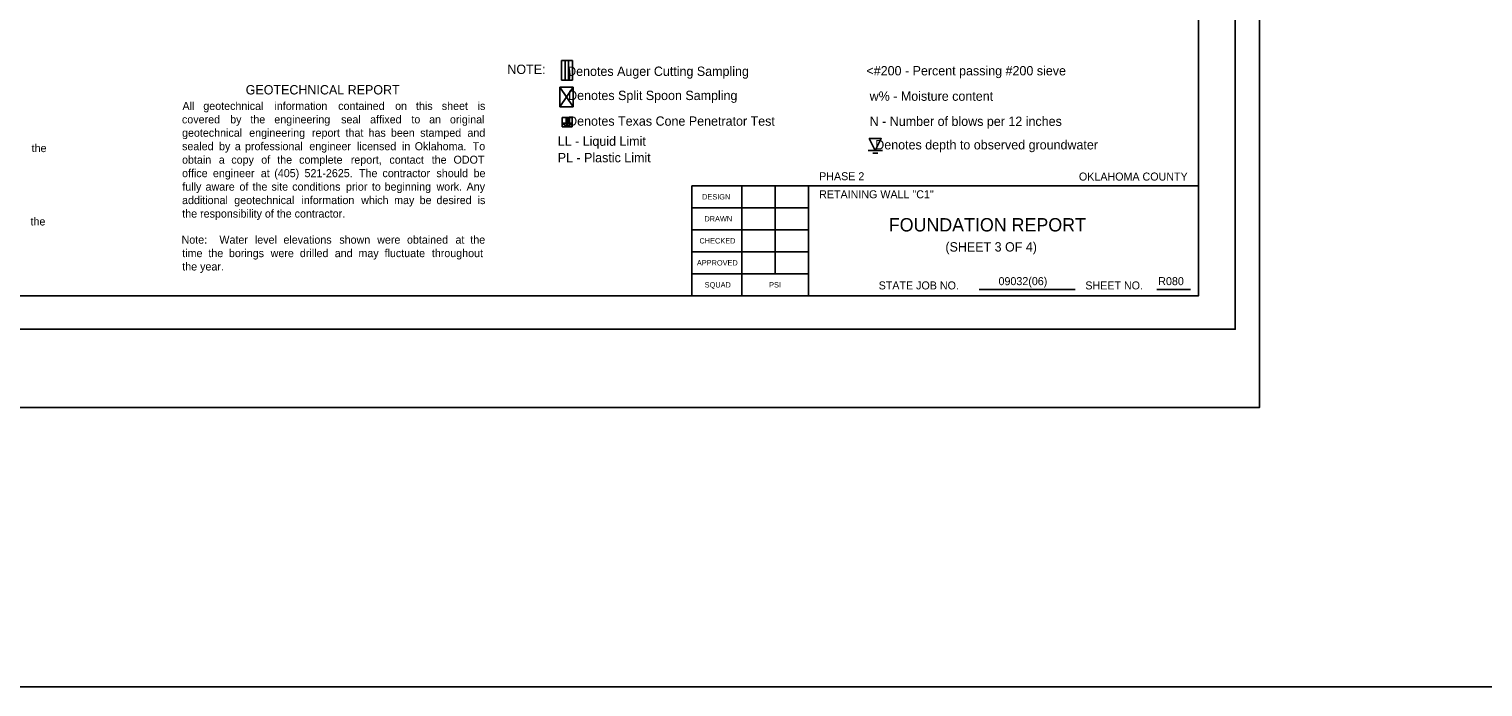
# Model space of a CAD drawing. Extents: x -6 to 173, y 24 to 64.
# Drawn here: x 107.52 to 129.33, y 25.78 to 35.65 of the extents above; entities that cross this region are included whole.
import ezdxf

# ---------------------------------------------------------------- set-up
doc = ezdxf.new("R2010")
doc.units = 0
for name, color, linetype in [('4', 7, 'Continuous'), ('S', 7, 'Continuous'), ('SHT_Plot_Shape_Full', 7, 'Continuous'), ('SHT_Plot_Shape_Half', 7, 'Continuous'), ('SHT_Sheet_Border', 7, 'Continuous'), ('SHT_Standard_Sheet_Lines', 7, 'Continuous'), ('SHT_Standard_Sheet_Txt', 7, 'Continuous'), ('T', 7, 'Continuous'), ('T-5', 7, 'Continuous'), ('Text', 7, 'Continuous')]:
    doc.layers.add(name, color=color, linetype=linetype)

# ---------------------------------------------------------------- blocks, each defined once
blk = doc.blocks.new('DGRFC_WTLEV1_1')
for points in [[(-0.005, 0), (0.005, 0)], [(0, 0), (0.0042, 0.0083), (-0.0042, 0.0083), (0, 0)], [(-0.0017, -0.0017), (0.0017, -0.0017)]]:
    blk.add_lwpolyline(points)

msp = doc.modelspace()

# ---------------------------------------------------------------- linework, layer by layer
msp.add_line((115.51, 35.172), (115.51, 34.881))
for points in [[(115.51, 35.172), (115.676, 35.172)], [(115.676, 34.881), (115.676, 35.172)], [(115.51, 34.881), (115.676, 34.881)], [(115.51, 34.881), (115.676, 34.881)]]:
    msp.add_lwpolyline(points)
for points in [[(115.568, 35.172), (115.568, 34.881), (115.618, 34.881), (115.618, 35.172)], [(115.633, 35.005), (115.627, 35.047), (115.618, 35.087), (115.633, 35.005)], [(115.618, 35.087), (115.618, 34.881), (115.633, 35.005), (115.618, 35.087)], [(115.618, 34.881), (115.633, 34.922), (115.633, 35.005), (115.618, 34.881)], [(115.618, 34.881), (115.627, 34.881), (115.633, 34.922), (115.618, 34.881)], [(115.633, 34.922), (115.635, 34.963), (115.633, 35.005), (115.633, 34.922)]]:
    msp.add_lwpolyline(points, close=True)
at = {"layer": 'S'}
msp.add_lwpolyline([(-6.024, 64.421), (172.576, 64.421), (172.576, 25.783), (-6.024, 25.783)], close=True, dxfattribs=at)
at = {"layer": 'SHT_Plot_Shape_Full'}
msp.add_lwpolyline([(89.979, 53.971), (125.979, 53.971), (125.979, 29.971), (89.979, 29.971)], close=True, dxfattribs=at)
at = {"layer": 'SHT_Plot_Shape_Half'}
msp.add_lwpolyline([(91.616, 53.146), (125.616, 53.146), (125.616, 31.146), (91.616, 31.146)], close=True, dxfattribs=at)
at = {"layer": 'SHT_Sheet_Border'}
for p, q in [((117.466, 31.646), (117.466, 33.296)), ((117.466, 33.296), (125.066, 33.296)), ((119.216, 31.646), (119.216, 33.297))]:
    msp.add_line(p, q, dxfattribs=at)
msp.add_lwpolyline([(93.566, 52.646), (125.066, 52.646), (125.066, 31.646), (93.566, 31.646)], close=True, dxfattribs=at)
at = {"layer": 'SHT_Standard_Sheet_Lines'}
for p, q in [((118.216, 31.646), (118.216, 33.297)), ((118.716, 31.976), (118.716, 33.297)), ((121.777, 31.742), (123.217, 31.742)), ((124.442, 31.742), (124.944, 31.742))]:
    msp.add_line(p, q, dxfattribs=at)
for points in [[(119.216, 32.966), (117.466, 32.966)], [(119.216, 32.636), (117.466, 32.636)], [(119.216, 32.306), (117.466, 32.306)], [(119.216, 31.976), (117.466, 31.976)]]:
    msp.add_lwpolyline(points, dxfattribs=at)
at = {"layer": 'Text'}
for p, q in [((115.486, 34.481), (115.486, 34.773)), ((115.522, 34.181), (115.522, 34.322))]:
    msp.add_line(p, q, dxfattribs=at)
for points in [[(115.486, 34.481), (115.686, 34.773)], [(115.486, 34.773), (115.686, 34.481)], [(115.486, 34.773), (115.686, 34.773)], [(115.686, 34.481), (115.686, 34.773)], [(115.486, 34.481), (115.686, 34.481)], [(115.522, 34.322), (115.672, 34.322)], [(115.672, 34.181), (115.672, 34.322)], [(115.522, 34.181), (115.672, 34.181)]]:
    msp.add_lwpolyline(points, dxfattribs=at)
for points in [[(115.582, 34.237), (115.612, 34.322), (115.582, 34.322), (115.582, 34.237)], [(115.582, 34.237), (115.612, 34.237), (115.612, 34.322), (115.582, 34.237)], [(115.582, 34.237), (115.522, 34.237), (115.597, 34.181), (115.582, 34.237)], [(115.582, 34.237), (115.597, 34.181), (115.612, 34.237), (115.582, 34.237)], [(115.597, 34.181), (115.672, 34.237), (115.612, 34.237), (115.597, 34.181)]]:
    msp.add_lwpolyline(points, close=True, dxfattribs=at)

# ---------------------------------------------------------------- block references
at = {"layer": 'Text', "xscale": 21.6, "yscale": 21.6}
msp.add_blockref('DGRFC_WTLEV1_1', (120.217, 33.823), dxfattribs=at)

# ---------------------------------------------------------------- texts
at = {"layer": '4'}
msp.add_text('FOUNDATION REPORT', height=0.2, dxfattribs=at).set_placement((120.42, 32.611))
at = {"layer": 'SHT_Standard_Sheet_Txt'}
for s, height, p in [('DESIGN', 0.08, (117.619, 33.091)), ('DRAWN', 0.08, (117.654, 32.761)), ('CHECKED', 0.08, (117.58, 32.431)), ('APPROVED', 0.08, (117.541, 32.101)), ('SQUAD', 0.08, (117.658, 31.771)), ('PSI', 0.08, (118.625, 31.771)), ('STATE JOB NO.', 0.12, (120.268, 31.742)), ('SHEET NO. ', 0.12, (123.368, 31.742))]:
    msp.add_text(s, height=height, dxfattribs=at).set_placement(p)
at = {"layer": 'T'}
for s, p in [('PHASE 2', (119.375, 33.379)), ('OKLAHOMA COUNTY', (123.272, 33.374)), ('RETAINING WALL "C1" ', (119.375, 33.108)), ('09032(06)', (122.066, 31.806)), ('R080', (124.462, 31.806))]:
    msp.add_text(s, height=0.12, dxfattribs=at).set_placement(p)
at = {"layer": 'T-5'}
msp.add_text('(SHEET 3 OF 4)', height=0.14, dxfattribs=at).set_placement((121.269, 32.31))
at = {"layer": 'Text'}
for s, height, p in [('NOTE:', 0.14, (114.699, 34.972)), ('    Denotes Auger Cutting Sampling', 0.14, (115.387, 34.943)), (' <#200 - Percent passing #200 sieve', 0.14, (120.033, 34.951)), ('GEOTECHNICAL REPORT', 0.14, (110.774, 34.665)), ('    Denotes Split Spoon Sampling', 0.14, (115.402, 34.581)), ('w% - Moisture content', 0.14, (120.133, 34.57)), ('All', 0.12, (109.825, 34.433)), ('geotechnical', 0.12, (110.138, 34.433)), ('information', 0.12, (111.205, 34.433)), ('contained', 0.12, (112.161, 34.433)), ('on', 0.12, (113.015, 34.433)), ('this', 0.12, (113.328, 34.433)), ('sheet', 0.12, (113.715, 34.433)), ('is ', 0.12, (114.252, 34.433)), ('covered', 0.12, (109.818, 34.231)), ('by', 0.12, (110.541, 34.231)), ('the', 0.12, (110.844, 34.231)), ('engineering', 0.12, (111.203, 34.231)), ('seal', 0.12, (112.205, 34.231)), ('affixed', 0.12, (112.639, 34.231)), ('to', 0.12, (113.259, 34.231)), ('an', 0.12, (113.525, 34.231)), ('original ', 0.12, (113.838, 34.231)), ('    Denotes Texas Cone Penetrator Test', 0.14, (115.402, 34.196)), ('N - Number of blows per 12 inches', 0.14, (120.133, 34.193)), ('geotechnical', 0.12, (109.819, 34.031)), ('engineering', 0.12, (110.826, 34.031)), ('report', 0.12, (111.768, 34.031)), ('that', 0.12, (112.271, 34.031)), ('has', 0.12, (112.616, 34.031)), ('been', 0.12, (112.952, 34.031)), ('stamped', 0.12, (113.391, 34.031)), ('and ', 0.12, (114.099, 34.031)), (' LL - Liquid Limit', 0.14, (115.402, 33.895)), ('the ', 0.12, (107.563, 33.801)), ('sealed', 0.12, (109.819, 33.829)), ('by', 0.12, (110.374, 33.829)), ('a', 0.12, (110.611, 33.829)), ('professional', 0.12, (110.764, 33.829)), ('engineer', 0.12, (111.728, 33.829)), ('licensed', 0.12, (112.443, 33.829)), ('in', 0.12, (113.118, 33.829)), ('Oklahoma.', 0.12, (113.309, 33.829)), ('To ', 0.12, (114.179, 33.829)), ('    Denotes depth to observed groundwater', 0.14, (120.009, 33.841)), ('obtain', 0.12, (109.819, 33.627)), ('a', 0.12, (110.37, 33.627)), ('copy', 0.12, (110.558, 33.627)), ('of', 0.12, (111.007, 33.627)), ('the', 0.12, (111.247, 33.627)), ('complete', 0.12, (111.575, 33.627)), ('report,', 0.12, (112.35, 33.627)), ('contact', 0.12, (112.929, 33.627)), ('the', 0.12, (113.564, 33.627)), ('ODOT ', 0.12, (113.891, 33.627)), (' PL - Plastic Limit', 0.14, (115.402, 33.648)), ('office', 0.12, (109.819, 33.425)), ('engineer', 0.12, (110.282, 33.425)), ('at', 0.12, (111, 33.425)), ('(405)', 0.12, (111.202, 33.425)), ('521-2625.', 0.12, (111.656, 33.425)), ('The', 0.12, (112.473, 33.425)), ('contractor', 0.12, (112.825, 33.425)), ('should', 0.12, (113.635, 33.425)), ('be ', 0.12, (114.192, 33.425)), ('fully', 0.12, (109.823, 33.223)), ('aware', 0.12, (110.172, 33.223)), ('of', 0.12, (110.68, 33.223)), ('the', 0.12, (110.876, 33.223)), ('site', 0.12, (111.16, 33.223)), ('conditions', 0.12, (111.472, 33.223)), ('prior', 0.12, (112.278, 33.223)), ('to', 0.12, (112.667, 33.223)), ('beginning', 0.12, (112.858, 33.223)), ('work.', 0.12, (113.636, 33.223)), ('Any ', 0.12, (114.087, 33.223)), ('the responsibility of the contractor.', 0.12, (109.822, 32.819)), ('additional', 0.12, (109.819, 33.021)), ('geotechnical', 0.12, (110.602, 33.021)), ('information', 0.12, (111.61, 33.021)), ('which', 0.12, (112.506, 33.021)), ('may', 0.12, (113, 33.021)), ('be', 0.12, (113.383, 33.021)), ('desired', 0.12, (113.636, 33.021)), ('is ', 0.12, (114.252, 33.021)), ('the ', 0.12, (107.546, 32.701)), ('Note:', 0.12, (109.812, 32.428)), ('Water', 0.12, (110.379, 32.428)), ('level', 0.12, (110.912, 32.428)), ('elevations', 0.12, (111.34, 32.428)), ('shown', 0.12, (112.178, 32.428)), ('were', 0.12, (112.746, 32.428)), ('obtained', 0.12, (113.193, 32.428)), ('at', 0.12, (113.92, 32.428)), ('the ', 0.12, (114.143, 32.428)), ('time', 0.12, (109.822, 32.226)), ('the', 0.12, (110.214, 32.226)), ('borings', 0.12, (110.522, 32.226)), ('were', 0.12, (111.148, 32.226)), ('drilled', 0.12, (111.587, 32.226)), ('and', 0.12, (112.109, 32.226)), ('may', 0.12, (112.465, 32.226)), ('fluctuate', 0.12, (112.857, 32.226)), ('throughout ', 0.12, (113.566, 32.226)), ('the year.', 0.12, (109.822, 32.026))]:
    msp.add_text(s, height=height, dxfattribs=at).set_placement(p)

doc.saveas('drawing.dxf')
